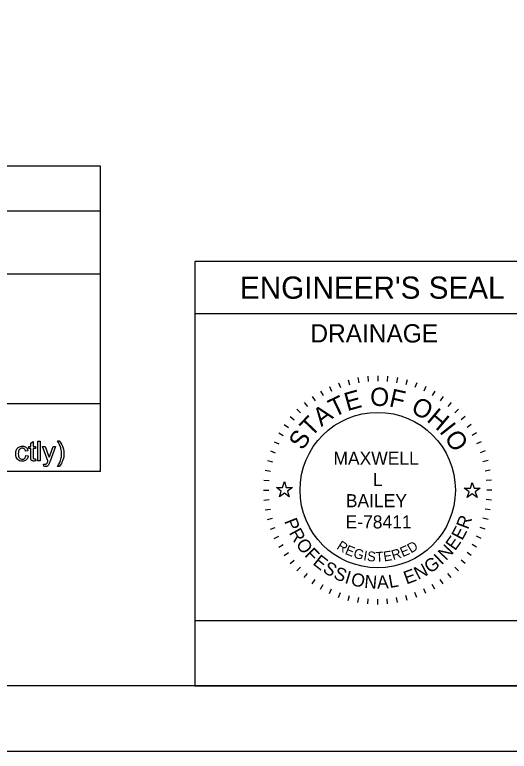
# Model space of a CAD drawing. Extents: x 0 to 34, y 0 to 22.
# Drawn here: x 5.97 to 9.76, y 0 to 5.64 of the extents above; entities that cross this region are included whole.
import ezdxf

# ---------------------------------------------------------------- set-up
doc = ezdxf.new("R2010")
doc.units = 0
for name, color, linetype in [('SH_Border', 7, 'Continuous'), ('SH_Cut_Line', 7, 'Continuous'), ('SH_Data', 7, 'Continuous'), ('SH_Text', 7, 'Continuous')]:
    doc.layers.add(name, color=color, linetype=linetype)

msp = doc.modelspace()

# ---------------------------------------------------------------- linework, layer by layer
at = {"layer": 'SH_Border'}
msp.add_lwpolyline([(1.5, 21.498), (33.5, 21.498), (33.5, 0.498), (1.5, 0.498)], close=True, dxfattribs=at)
at = {"layer": 'SH_Cut_Line'}
msp.add_lwpolyline([(0, -0.002), (34, -0.002), (34, 21.998), (0, 21.998)], close=True, dxfattribs=at)
at = {"layer": 'SH_Data'}
for p, q in [((6.6275, 4.4783), (2.3775, 4.4783)), ((6.6275, 2.1408), (6.6275, 4.4783)), ((2.3775, 4.1367), (6.6275, 4.1367)), ((10.15, 3.748), (7.35, 3.748)), ((7.35, 3.748), (7.35, 0.498)), ((2.3775, 3.6533), (6.6275, 3.6533)), ((10.15, 3.348), (7.35, 3.348)), ((8.4507, 2.8202), (8.4644, 2.7826)), ((8.5235, 2.8432), (8.5339, 2.8045)), ((8.5981, 2.8597), (8.605, 2.8203)), ((8.6737, 2.8697), (8.6772, 2.8298)), ((8.75, 2.873), (8.75, 2.833)), ((8.8263, 2.8697), (8.8228, 2.8298)), ((8.9019, 2.8597), (8.895, 2.8203)), ((8.9765, 2.8432), (8.9661, 2.8045)), ((9.0493, 2.8202), (9.0356, 2.7826)), ((8.3802, 2.791), (8.3971, 2.7548)), ((9.1198, 2.791), (9.1029, 2.7548)), ((8.2481, 2.7148), (8.2711, 2.682)), ((8.3125, 2.7558), (8.3325, 2.7211)), ((9.1875, 2.7558), (9.1675, 2.7211)), ((9.2519, 2.7148), (9.2289, 2.682)), ((6.6275, 2.6587), (2.3775, 2.6587)), ((8.1876, 2.6683), (8.2133, 2.6376)), ((9.3124, 2.6683), (9.2867, 2.6376)), ((8.1313, 2.6167), (8.1596, 2.5884)), ((9.3687, 2.6167), (9.3404, 2.5884)), ((8.0797, 2.5604), (8.1104, 2.5347)), ((9.4203, 2.5604), (9.3896, 2.5347)), ((8.0332, 2.4999), (8.066, 2.4769)), ((9.4668, 2.4999), (9.434, 2.4769)), ((7.9922, 2.4355), (8.0269, 2.4155)), ((9.5078, 2.4355), (9.4731, 2.4155)), ((7.957, 2.3678), (7.9932, 2.3509)), ((9.543, 2.3678), (9.5068, 2.3509)), ((7.9278, 2.2973), (7.9654, 2.2836)), ((9.5722, 2.2973), (9.5346, 2.2836)), ((7.9048, 2.2245), (7.9435, 2.2141)), ((9.5952, 2.2245), (9.5565, 2.2141)), ((7.8883, 2.1499), (7.9277, 2.143)), ((9.6117, 2.1499), (9.5723, 2.143)), ((6.6275, 2.1408), (2.3775, 2.1408)), ((7.8783, 2.0743), (7.9182, 2.0708)), ((9.6217, 2.0743), (9.5818, 2.0708)), ((7.875, 1.998), (7.915, 1.998)), ((9.625, 1.998), (9.585, 1.998)), ((7.8783, 1.9217), (7.9182, 1.9252)), ((9.6217, 1.9217), (9.5818, 1.9252)), ((7.8883, 1.8461), (7.9277, 1.853)), ((9.6117, 1.8461), (9.5723, 1.853)), ((7.9048, 1.7715), (7.9435, 1.7819)), ((9.5952, 1.7715), (9.5565, 1.7819)), ((7.9278, 1.6987), (7.9654, 1.7124)), ((9.5722, 1.6987), (9.5346, 1.7124)), ((7.957, 1.6282), (7.9932, 1.6451)), ((9.543, 1.6282), (9.5068, 1.6451)), ((7.9922, 1.5605), (8.0269, 1.5805)), ((9.5078, 1.5605), (9.4731, 1.5805)), ((8.0332, 1.4961), (8.066, 1.5191)), ((9.4668, 1.4961), (9.434, 1.5191)), ((8.0797, 1.4356), (8.1104, 1.4613)), ((9.4203, 1.4356), (9.3896, 1.4613)), ((8.1313, 1.3793), (8.1596, 1.4076)), ((8.1876, 1.3277), (8.2133, 1.3584)), ((9.3124, 1.3277), (9.2867, 1.3584)), ((9.3687, 1.3793), (9.3404, 1.4076)), ((8.2481, 1.2812), (8.2711, 1.314)), ((9.2519, 1.2812), (9.2289, 1.314)), ((8.3125, 1.2402), (8.3325, 1.2749)), ((8.3802, 1.205), (8.3971, 1.2412)), ((9.1198, 1.205), (9.1029, 1.2412)), ((9.1875, 1.2402), (9.1675, 1.2749)), ((8.4507, 1.1758), (8.4644, 1.2134)), ((8.5235, 1.1528), (8.5339, 1.1915)), ((8.9765, 1.1528), (8.9661, 1.1915)), ((9.0493, 1.1758), (9.0356, 1.2134)), ((8.5981, 1.1363), (8.605, 1.1757)), ((8.6737, 1.1263), (8.6772, 1.1662)), ((8.75, 1.123), (8.75, 1.163)), ((8.8263, 1.1263), (8.8228, 1.1662)), ((8.9019, 1.1363), (8.895, 1.1757)), ((10.15, 0.498), (7.35, 0.498))]:
    msp.add_line(p, q, dxfattribs=at)
for points in [[(7.9736, 2.018), (8.0205, 2.018), (8.035, 2.0625), (8.0495, 2.018), (8.0964, 2.018), (8.0585, 1.9904), (8.073, 1.9458), (8.035, 1.9734), (7.997, 1.9458), (8.0115, 1.9904)], [(9.4127, 2.0126), (9.4596, 2.0126), (9.4741, 2.0571), (9.4886, 2.0126), (9.5355, 2.0126), (9.4976, 1.985), (9.5121, 1.9404), (9.4741, 1.968), (9.4361, 1.9404), (9.4506, 1.985)], [(10.15, 0.498), (10.15, 0.998), (7.35, 0.998), (7.35, 0.498)]]:
    msp.add_lwpolyline(points, close=True, dxfattribs=at)
msp.add_circle((8.75, 1.998), 0.595, dxfattribs=at)
at = {"layer": 'SH_Text'}
for points in [[(6.092, 2.2538), (6.092, 2.3165), (6.0784, 2.3165), (6.0784, 2.3308), (6.092, 2.3308), (6.092, 2.3577), (6.1105, 2.3688), (6.1105, 2.3308), (6.1289, 2.3308), (6.1289, 2.3165), (6.1105, 2.3165), (6.1105, 2.2527)], [(6.1465, 2.2219), (6.1465, 2.3721), (6.1649, 2.3721), (6.1649, 2.2219), (6.1465, 2.2219)], [(6.2974, 2.3746), (6.3105, 2.3746)], [(6.2243, 2.2218), (6.183, 2.3308), (6.2029, 2.3308), (6.2255, 2.2679)], [(6.241, 2.2673), (6.2643, 2.3308), (6.2827, 2.3308), (6.2414, 2.22)], [(6.0712, 2.2987), (6.0532, 2.296)], [(6.0548, 2.2618), (6.0729, 2.2593)], [(6.1289, 2.2384), (6.1315, 2.2221)], [(6.1928, 2.1801), (6.1907, 2.1975)], [(6.3105, 2.1777), (6.2974, 2.1777)]]:
    msp.add_lwpolyline(points, dxfattribs=at)
for points in [[(6.2974, 2.1777), (6.3279, 2.2269), (6.3279, 2.2762), (6.3279, 2.2954), (6.3235, 2.3144), (6.32, 2.3297), (6.3138, 2.3439), (6.3098, 2.3531), (6.2974, 2.3746)], [(6.3105, 2.3746), (6.3298, 2.3489), (6.339, 2.323), (6.3469, 2.3006), (6.3469, 2.2763), (6.3469, 2.2486), (6.3363, 2.2228), (6.3257, 2.197), (6.3105, 2.1777)], [(6.0729, 2.2593), (6.07, 2.2407), (6.0577, 2.2301), (6.0455, 2.2195), (6.0277, 2.2195), (6.0053, 2.2195), (5.9917, 2.2341), (5.9782, 2.2487), (5.9782, 2.2759), (5.9782, 2.2935), (5.984, 2.3068), (5.9899, 2.32), (6.0018, 2.3266), (6.0137, 2.3332), (6.0278, 2.3332), (6.0455, 2.3332), (6.0568, 2.3242), (6.068, 2.3152), (6.0712, 2.2987)], [(6.0532, 2.296), (6.0507, 2.307), (6.0442, 2.3125), (6.0377, 2.3181), (6.0285, 2.3181), (6.0146, 2.3181), (6.0059, 2.3081), (5.9972, 2.2981), (5.9972, 2.2764), (5.9972, 2.2545), (6.0056, 2.2446), (6.014, 2.2346), (6.0275, 2.2346), (6.0384, 2.2346), (6.0456, 2.2413), (6.0529, 2.2479), (6.0548, 2.2618)], [(6.2255, 2.2679), (6.2299, 2.256), (6.2334, 2.2428), (6.2366, 2.2552), (6.241, 2.2673)], [(6.1315, 2.2221), (6.1238, 2.2204), (6.1176, 2.2204), (6.1076, 2.2204), (6.1021, 2.2236), (6.0965, 2.2268), (6.0943, 2.232), (6.092, 2.2372), (6.092, 2.2538)], [(6.1105, 2.2527), (6.1105, 2.2448), (6.1114, 2.2425), (6.1124, 2.2403), (6.1146, 2.2389), (6.1168, 2.2376), (6.1209, 2.2376), (6.1239, 2.2376), (6.1289, 2.2384)], [(6.1907, 2.1975), (6.1967, 2.1958), (6.2012, 2.1958), (6.2074, 2.1958), (6.211, 2.1979), (6.2147, 2.1999), (6.2171, 2.2036), (6.2188, 2.2064), (6.2227, 2.2173), (6.2232, 2.2189), (6.2243, 2.2218)], [(6.2414, 2.22), (6.2348, 2.2022), (6.2311, 2.1954), (6.2262, 2.1863), (6.2198, 2.1821), (6.2135, 2.1779), (6.2046, 2.1779), (6.1993, 2.1779), (6.1928, 2.1801)]]:
    msp.add_open_spline(points, degree=3, dxfattribs=at)

# ---------------------------------------------------------------- texts
at = {"layer": 'SH_Data'}
for s, height, p in [("ENGINEER'S SEAL", 0.17, (7.6948, 3.463)), ('DRAINAGE', 0.14, (8.2347, 3.128)), ('MAXWELL', 0.1, (8.4109, 2.1917)), ('L', 0.1, (8.7136, 2.0292)), ('BAILEY', 0.1, (8.5059, 1.8667)), ('E-78411', 0.1, (8.504, 1.7042))]:
    msp.add_text(s, height=height, dxfattribs=at).set_placement(p)
for s, height, rotation, p in [('E', 0.14, 15.7571, (8.5169, 2.6014)), ('O', 0.14, 359.7812, (8.692, 2.6422)), ('F', 0.14, 347.4362, (8.8311, 2.6397)), ('T', 0.14, 25.7167, (8.4161, 2.552)), ('O', 0.14, 332.2586, (8.9963, 2.5961)), ('A', 0.14, 36.4747, (8.3185, 2.4799)), ('H', 0.14, 319.9136, (9.1184, 2.5296)), ('T', 0.14, 46.4344, (8.2417, 2.398)), ('I', 0.14, 308.367, (9.2174, 2.4451)), ('S', 0.14, 57.1924, (8.176, 2.2961)), ('O', 0.14, 303.1491, (9.2561, 2.4008)), ('P', 0.1, 291.494, (8.0323, 1.7599)), ('R', 0.1, 69.2322, (9.4413, 1.6916)), ('R', 0.1, 298.7311, (8.0681, 1.6713)), ('E', 0.1, 61.9951, (9.3972, 1.607)), ('E', 0.1, 54.758, (9.3428, 1.5286)), ('O', 0.1, 306.4666, (8.1182, 1.5825)), ('R', 0.075, 327.8239, (8.4301, 1.552)), ('D', 0.075, 31.466, (9.005, 1.5116)), ('N', 0.1, 47.0224, (9.2742, 1.453)), ('F', 0.1, 314.7068, (8.1843, 1.4963)), ('E', 0.075, 337.7777, (8.4939, 1.5108)), ('G', 0.075, 344.2727, (8.5582, 1.4828)), ('I', 0.075, 350.6464, (8.6368, 1.4614)), ('S', 0.075, 353.7858, (8.6655, 1.4561)), ('T', 0.075, 3.0061, (8.7352, 1.4485)), ('E', 0.075, 8.9826, (8.7992, 1.451)), ('R', 0.075, 17.6836, (8.8687, 1.4607)), ('E', 0.075, 23.3052, (8.9409, 1.4836)), ('E', 0.1, 321.4393, (8.247, 1.4334)), ('G', 0.1, 35.0469, (9.1497, 1.3561)), ('I', 0.1, 43.287, (9.2376, 1.4201)), ('S', 0.1, 328.6764, (8.3222, 1.3746)), ('N', 0.1, 27.3113, (9.0597, 1.3082)), ('S', 0.1, 335.9134, (8.4041, 1.3256)), ('I', 0.1, 343.1505, (8.4916, 1.2874)), ('O', 0.1, 346.8859, (8.5384, 1.2721)), ('E', 0.1, 20.0742, (8.9703, 1.2747)), ('N', 0.1, 355.1261, (8.6446, 1.2492)), ('A', 0.1, 2.8617, (8.7464, 1.2419)), ('L', 0.1, 10.0987, (8.8417, 1.2474))]:
    msp.add_text(s, height=height, rotation=rotation, dxfattribs=at).set_placement(p)

doc.saveas('drawing.dxf')
